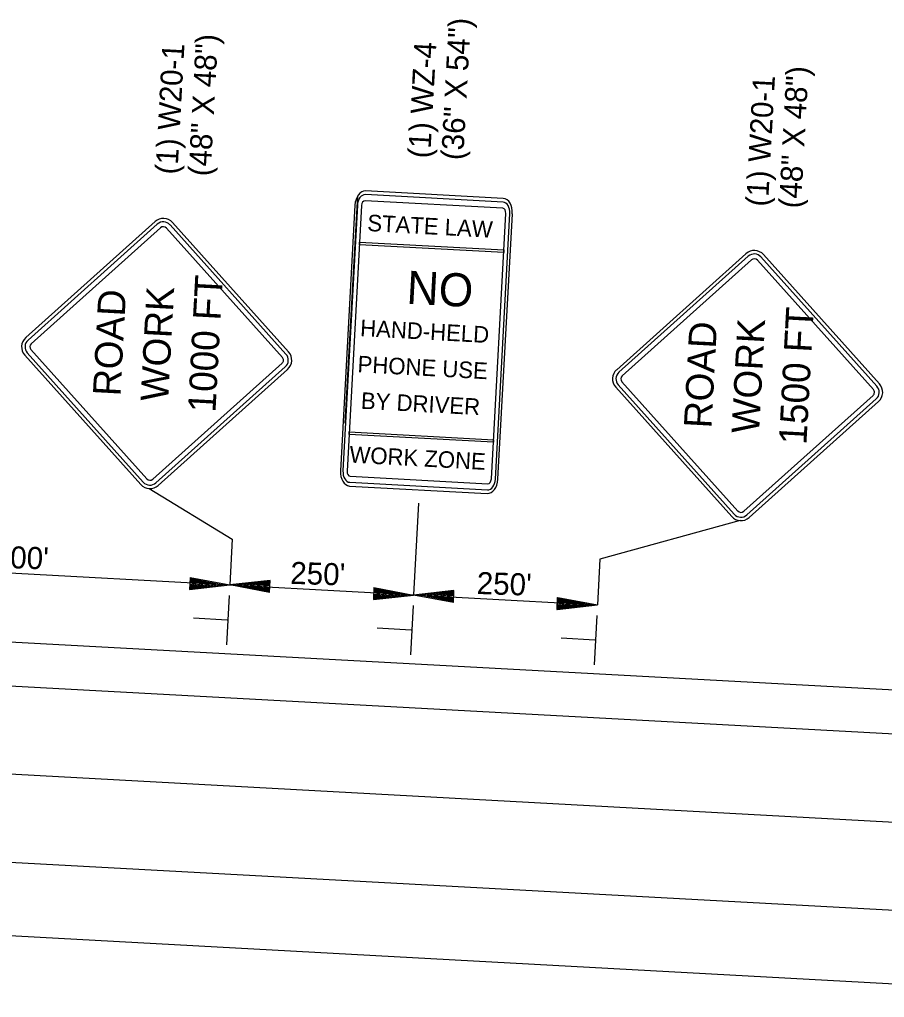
# Model space of a CAD drawing. Extents: x 879461 to 881100, y 1566470 to 1567598.
# Drawn here: x 880623.3 to 880858.5, y 1567117.2 to 1567383.2 of the extents above; entities that cross this region are included whole.
import ezdxf

# ---------------------------------------------------------------- set-up
doc = ezdxf.new("R2010")
doc.units = 0
for name, color, linetype in [('P_TC_Signs_Permanent', 7, 'Continuous'), ('P_TC_Signs_Temporary', 7, 'Continuous'), ('R_Annotation', 7, 'Continuous'), ('R_Draft', 7, 'Continuous')]:
    doc.layers.add(name, color=color, linetype=linetype)

msp = doc.modelspace()

# ---------------------------------------------------------------- linework, layer by layer
at = {"layer": 'P_TC_Signs_Permanent'}
for p, q in [((880754.77, 1567333.49), (880717.31, 1567335.53)), ((880754.82, 1567334.5), (880717.36, 1567336.53)), ((880714.47, 1567332.67), (880710.54, 1567260.42)), ((880715.14, 1567332.63), (880711.21, 1567260.39)), ((880716.25, 1567332.57), (880712.32, 1567260.32)), ((880754.68, 1567331.82), (880717.22, 1567333.86)), ((880751.57, 1567258.19), (880755.5, 1567330.43)), ((880752.68, 1567258.13), (880756.61, 1567330.37)), ((880753.35, 1567258.09), (880757.28, 1567330.34)), ((880713.14, 1567258.94), (880750.6, 1567256.9)), ((880713, 1567256.26), (880750.46, 1567254.23)), ((880713.05, 1567257.27), (880750.51, 1567255.23))]:
    msp.add_line(p, q, dxfattribs=at)
for centre, major_axis, start_param, end_param in [((880717.14, 1567332.52), (0.22, 4.01), 0, 1.570796), ((880717.14, 1567332.52), (0.16, 3.01), 0, 1.570796), ((880717.14, 1567332.52), (0.07, 1.34), 0, 1.570796), ((880754.6, 1567330.48), (0.16, 3.01), 4.712389, 6.283185), ((880754.6, 1567330.48), (0.22, 4.01), 4.712389, 6.283185), ((880754.6, 1567330.48), (0.07, 1.34), 4.712389, 6.283185), ((880713.22, 1567260.28), (-0.22, -4.01), 4.712389, 6.283185), ((880713.22, 1567260.28), (-0.16, -3.01), 4.712389, 6.283185), ((880713.22, 1567260.28), (-0.07, -1.34), 4.712389, 6.283185), ((880750.67, 1567258.24), (-0.22, -4.01), 0, 1.570796), ((880750.67, 1567258.24), (-0.16, -3.01), 0, 1.570796), ((880750.67, 1567258.24), (-0.07, -1.34), 0, 1.570796)]:
    msp.add_ellipse(centre, major_axis=major_axis, ratio=0.666667, start_param=start_param, end_param=end_param, dxfattribs=at)
at = {"layer": 'P_TC_Signs_Temporary'}
for p, q in [((880624.92, 1567296.65), (880660.1, 1567328.2)), ((880625.55, 1567295.95), (880660.72, 1567327.5)), ((880664.17, 1567327.31), (880695.71, 1567292.14)), ((880664.86, 1567327.94), (880696.41, 1567292.76)), ((880626.42, 1567294.98), (880661.6, 1567326.52)), ((880663.19, 1567326.44), (880694.74, 1567291.26)), ((880785.65, 1567287.91), (880820.82, 1567319.46)), ((880786.27, 1567287.21), (880821.45, 1567318.76)), ((880825.59, 1567319.2), (880857.14, 1567284.02)), ((880787.15, 1567286.24), (880822.33, 1567317.78)), ((880823.91, 1567317.7), (880855.46, 1567282.52)), ((880824.89, 1567318.57), (880856.44, 1567283.4)), ((880656.91, 1567257.33), (880625.36, 1567292.51)), ((880657.89, 1567258.21), (880626.34, 1567293.39)), ((880656.21, 1567256.71), (880624.66, 1567291.88)), ((880694.65, 1567289.67), (880659.47, 1567258.12)), ((880695.53, 1567288.69), (880660.35, 1567257.15)), ((880696.15, 1567288), (880660.98, 1567256.45)), ((880818.61, 1567249.47), (880787.06, 1567284.65)), ((880816.94, 1567247.97), (880785.39, 1567283.15)), ((880817.63, 1567248.6), (880786.09, 1567283.77)), ((880855.37, 1567280.93), (880820.2, 1567249.39)), ((880856.25, 1567279.96), (880821.08, 1567248.41)), ((880856.88, 1567279.26), (880821.7, 1567247.71))]:
    msp.add_line(p, q, dxfattribs=at)
for centre, radius, start, end in [((880662.35, 1567325.69), 3.38, 41.8871, 131.8871), ((880662.35, 1567325.69), 2.44, 41.8871, 131.8871), ((880662.35, 1567325.69), 1.12, 41.8871, 131.8871), ((880823.08, 1567316.95), 3.38, 41.8871, 131.8871), ((880823.08, 1567316.95), 2.44, 41.8871, 131.8871), ((880823.08, 1567316.95), 1.12, 41.8871, 131.8871), ((880627.18, 1567294.14), 3.38, 131.8871, 221.8871), ((880627.18, 1567294.14), 2.44, 131.8871, 221.8871), ((880627.18, 1567294.14), 1.13, 131.8871, 221.8871), ((880693.9, 1567290.51), 2.44, 311.8871, 41.8871), ((880693.9, 1567290.51), 3.38, 311.8871, 41.8871), ((880693.9, 1567290.51), 1.13, 311.8871, 41.8871), ((880787.9, 1567285.4), 3.38, 131.8871, 221.8871), ((880787.9, 1567285.4), 2.44, 131.8871, 221.8871), ((880787.9, 1567285.4), 1.13, 131.8871, 221.8871), ((880854.62, 1567281.77), 3.38, 311.8871, 41.8871), ((880854.62, 1567281.77), 1.13, 311.8871, 41.8871), ((880854.62, 1567281.77), 2.44, 311.8871, 41.8871), ((880658.72, 1567258.96), 1.12, 221.8871, 311.8871), ((880658.72, 1567258.96), 3.38, 221.8871, 311.8871), ((880658.72, 1567258.96), 2.44, 221.8871, 311.8871), ((880819.45, 1567250.22), 1.12, 221.8871, 311.8871), ((880819.45, 1567250.22), 3.38, 221.8871, 311.8871), ((880819.45, 1567250.22), 2.44, 221.8871, 311.8871)]:
    msp.add_arc(centre, radius, start, end, dxfattribs=at)
at = {"layer": 'R_Draft'}
for p, q in [((880711.85, 1567273.32), (880715.22, 1567335.19)), ((880715.67, 1567321.91), (880715.71, 1567322.61)), ((880754.92, 1567319.77), (880715.67, 1567321.91)), ((880715.71, 1567322.61), (880754.95, 1567320.48)), ((880754.95, 1567320.48), (880754.92, 1567319.77)), ((880712.87, 1567270.29), (880712.9, 1567271)), ((880712.9, 1567271), (880752.15, 1567268.86)), ((880752.11, 1567268.16), (880712.87, 1567270.29)), ((880752.15, 1567268.86), (880752.11, 1567268.16)), ((880658.54, 1567255.59), (880681.12, 1567241.85)), ((880731.79, 1567251.6), (880730.43, 1567226.63)), ((880819.26, 1567246.85), (880781.1, 1567236.41)), ((880681.12, 1567241.85), (880680.44, 1567229.36)), ((880781.1, 1567236.41), (880780.42, 1567223.93)), ((880580.59, 1567234.79), (880680.44, 1567229.36)), ((880669.64, 1567231.41), (880669.51, 1567228.15)), ((880669.61, 1567230.86), (880676.76, 1567229.51)), ((880669.63, 1567231.14), (880678.63, 1567229.43)), ((880669.64, 1567231.41), (880680.44, 1567229.36)), ((880669.51, 1567228.15), (880680.44, 1567229.36)), ((880669.52, 1567228.42), (880678.63, 1567229.43)), ((880669.53, 1567228.7), (880676.76, 1567229.51)), ((880669.54, 1567228.97), (880674.95, 1567229.57)), ((880669.55, 1567229.25), (880673.1, 1567229.65)), ((880669.56, 1567229.52), (880671.29, 1567229.71)), ((880669.58, 1567230.04), (880671.29, 1567229.71)), ((880669.59, 1567230.31), (880673.1, 1567229.65)), ((880669.6, 1567230.59), (880674.95, 1567229.57)), ((880691.38, 1567230.58), (880680.44, 1567229.36)), ((880691.38, 1567230.57), (880680.44, 1567229.36)), ((880680.44, 1567229.36), (880780.3, 1567223.96)), ((880691.25, 1567227.32), (880680.44, 1567229.36)), ((880691.25, 1567227.31), (880680.44, 1567229.36)), ((880691.37, 1567230.31), (880682.26, 1567229.3)), ((880691.37, 1567230.3), (880682.26, 1567229.29)), ((880691.26, 1567227.59), (880682.26, 1567229.3)), ((880691.26, 1567227.58), (880682.26, 1567229.29)), ((880691.36, 1567230.03), (880684.13, 1567229.22)), ((880691.36, 1567230.02), (880684.13, 1567229.22)), ((880691.27, 1567227.87), (880684.13, 1567229.22)), ((880691.27, 1567227.86), (880684.13, 1567229.22)), ((880691.35, 1567229.76), (880685.94, 1567229.16)), ((880691.35, 1567229.75), (880685.94, 1567229.15)), ((880691.28, 1567228.14), (880685.94, 1567229.16)), ((880691.28, 1567228.13), (880685.94, 1567229.15)), ((880691.34, 1567229.48), (880687.78, 1567229.08)), ((880691.34, 1567229.47), (880687.78, 1567229.08)), ((880691.29, 1567228.42), (880687.78, 1567229.08)), ((880691.29, 1567228.41), (880687.78, 1567229.08)), ((880691.33, 1567229.2), (880689.6, 1567229.02)), ((880691.33, 1567229.2), (880689.6, 1567229.01)), ((880691.3, 1567228.69), (880689.6, 1567229.02)), ((880691.31, 1567228.69), (880689.6, 1567229.01)), ((880691.25, 1567227.32), (880691.38, 1567230.58)), ((880691.25, 1567227.31), (880691.38, 1567230.57)), ((880719.62, 1567228.67), (880719.49, 1567225.41)), ((880719.61, 1567228.4), (880728.61, 1567226.69)), ((880719.62, 1567228.67), (880730.43, 1567226.62)), ((880680.29, 1567226.5), (880679.56, 1567213.05)), ((880719.49, 1567225.41), (880730.43, 1567226.62)), ((880719.5, 1567225.68), (880728.61, 1567226.69)), ((880719.51, 1567225.96), (880726.75, 1567226.77)), ((880719.52, 1567226.23), (880724.93, 1567226.83)), ((880719.54, 1567226.51), (880723.09, 1567226.91)), ((880719.55, 1567226.78), (880721.28, 1567226.97)), ((880719.57, 1567227.3), (880721.28, 1567226.97)), ((880719.58, 1567227.57), (880723.09, 1567226.91)), ((880719.59, 1567227.85), (880724.93, 1567226.83)), ((880719.6, 1567228.12), (880726.75, 1567226.77)), ((880741.37, 1567227.84), (880730.43, 1567226.62)), ((880741.24, 1567224.58), (880730.43, 1567226.62)), ((880741.36, 1567227.56), (880732.25, 1567226.56)), ((880741.25, 1567224.85), (880732.25, 1567226.56)), ((880741.35, 1567227.29), (880734.11, 1567226.48)), ((880741.26, 1567225.13), (880734.11, 1567226.48)), ((880741.33, 1567227.02), (880735.93, 1567226.42)), ((880741.27, 1567225.4), (880735.93, 1567226.42)), ((880741.32, 1567226.74), (880737.77, 1567226.34)), ((880741.28, 1567225.68), (880737.77, 1567226.34)), ((880741.31, 1567226.46), (880739.59, 1567226.28)), ((880741.3, 1567225.95), (880739.59, 1567226.28)), ((880741.24, 1567224.58), (880741.37, 1567227.84)), ((880769.49, 1567225.97), (880769.36, 1567222.71)), ((880769.61, 1567225.97), (880769.48, 1567222.71)), ((880769.48, 1567225.7), (880778.48, 1567223.99)), ((880769.49, 1567225.97), (880780.3, 1567223.93)), ((880769.6, 1567225.71), (880778.6, 1567223.99)), ((880769.61, 1567225.97), (880780.42, 1567223.93)), ((880730.27, 1567223.77), (880729.54, 1567210.32)), ((880769.36, 1567222.71), (880780.3, 1567223.93)), ((880769.37, 1567222.98), (880778.48, 1567223.99)), ((880769.38, 1567223.26), (880776.61, 1567224.07)), ((880769.39, 1567223.53), (880774.8, 1567224.14)), ((880769.4, 1567223.81), (880772.96, 1567224.21)), ((880769.41, 1567224.09), (880771.14, 1567224.28)), ((880769.44, 1567224.6), (880771.14, 1567224.28)), ((880769.45, 1567224.87), (880772.96, 1567224.21)), ((880769.46, 1567225.15), (880774.8, 1567224.14)), ((880769.47, 1567225.42), (880776.61, 1567224.07)), ((880769.48, 1567222.71), (880780.42, 1567223.93)), ((880769.49, 1567222.99), (880778.6, 1567223.99)), ((880769.5, 1567223.26), (880776.73, 1567224.07)), ((880769.51, 1567223.53), (880774.92, 1567224.14)), ((880769.52, 1567223.81), (880773.08, 1567224.21)), ((880769.53, 1567224.09), (880771.26, 1567224.28)), ((880769.55, 1567224.6), (880771.26, 1567224.28)), ((880769.57, 1567224.87), (880773.08, 1567224.21)), ((880769.58, 1567225.15), (880774.92, 1567224.14)), ((880769.59, 1567225.42), (880776.73, 1567224.07)), ((880932.7, 1567196.83), (880499.33, 1567220.4)), ((880679.73, 1567219.82), (880670.55, 1567220.32)), ((880780.26, 1567221.06), (880779.53, 1567207.62)), ((880729.72, 1567217.08), (880720.54, 1567217.58)), ((880779.7, 1567214.38), (880770.53, 1567214.88)), ((880932.05, 1567184.88), (880498.68, 1567208.45)), ((880930.75, 1567160.97), (880497.38, 1567184.54)), ((880929.45, 1567137.07), (880496.08, 1567160.64)), ((880928.37, 1567117.15), (880495, 1567140.72))]:
    msp.add_line(p, q, dxfattribs=at)

# ---------------------------------------------------------------- texts
at = {"layer": 'P_TC_Signs_Permanent'}
for s, height, p in [('STATE LAW', 4.5, (880717.75, 1567325.64)), ('NO', 9, (880728.37, 1567305.88)), ('HAND-HELD', 4.5, (880715.8, 1567297.06)), ('PHONE USE', 4.5, (880715.09, 1567287.23)), ('BY DRIVER', 4.5, (880716, 1567277.3)), ('WORK ZONE', 4.5, (880712.88, 1567262.66))]:
    msp.add_text(s, height=height, rotation=356.8871, dxfattribs=at).set_placement(p)
at = {"layer": 'P_TC_Signs_Temporary'}
for s, p in [('1000 FT', (880676.52, 1567276.14)), (' ROAD ', (880650.52, 1567277.82)), ('WORK', (880663.64, 1567279.15)), ('1500 FT', (880837.24, 1567267.4)), (' ROAD ', (880811.25, 1567269.09)), ('WORK', (880824.36, 1567270.41))]:
    msp.add_text(s, height=7.5, rotation=86.8871, dxfattribs=at).set_placement(p)
at = {"layer": 'R_Annotation'}
for s, p in [('(36" X 54")', (880743.91, 1567344.82)), ('(48" X 48")', (880675.17, 1567340.43)), ('(1) W20-1', (880666.18, 1567340.92)), ('(1) WZ-4', (880734.92, 1567345.31)), ('(48" X 48")', (880835.77, 1567331.7)), ('(1) W20-1', (880826.79, 1567332.19))]:
    msp.add_text(s, height=6, rotation=86.8871, dxfattribs=at).set_placement(p)
at = {"layer": 'R_Draft'}
for s, p in [("500'", (880616.19, 1567234.05)), ("250'", (880696.82, 1567229.67)), ("250'", (880747.52, 1567226.91))]:
    msp.add_text(s, height=6, rotation=358.1175, dxfattribs=at).set_placement(p)

doc.saveas('drawing.dxf')
